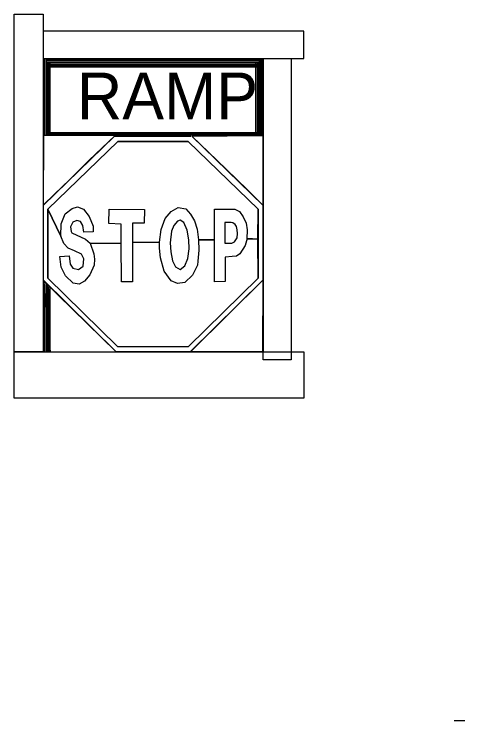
# Model space of a CAD drawing. Extents: x -0.162 to 0.195, y -0.006 to 0.263.
# Drawn here: x -0.1625 to -0.015, y -0.0064 to 0.2249 of the extents above; entities that cross this region are included whole.
import ezdxf

# ---------------------------------------------------------------- set-up
doc = ezdxf.new("R2010")
doc.units = 0
doc.layers.add('1', color=7, linetype='Continuous')
doc.layers.add('3', color=7, linetype='Continuous')

msp = doc.modelspace()

# ---------------------------------------------------------------- linework, layer by layer
at = {"layer": '1'}
msp.add_line((-0.015, -0.00638), (-0.0185, -0.00638), dxfattribs=at)
at = {"layer": '3'}
for p, q in [((-0.153, 0.21038), (-0.081, 0.21038)), ((-0.153, 0.21038), (-0.153, 0.11438)), ((-0.15275, 0.18488), (-0.15275, 0.21025)), ((-0.15238, 0.18513), (-0.15238, 0.21025)), ((-0.15188, 0.185), (-0.15188, 0.21025)), ((-0.15175, 0.21013), (-0.08188, 0.21013)), ((-0.15175, 0.20975), (-0.08188, 0.20975)), ((-0.15175, 0.20925), (-0.08188, 0.20925)), ((-0.1515, 0.20888), (-0.0825, 0.20888)), ((-0.1515, 0.185), (-0.1515, 0.20888)), ((-0.1515, 0.20838), (-0.0825, 0.20838)), ((-0.15113, 0.18613), (-0.15113, 0.20888)), ((-0.15063, 0.18613), (-0.15063, 0.20888)), ((-0.08338, 0.18613), (-0.08338, 0.20888)), ((-0.08288, 0.18613), (-0.08288, 0.20888)), ((-0.0825, 0.185), (-0.0825, 0.20888)), ((-0.08213, 0.185), (-0.08213, 0.21025)), ((-0.08175, 0.18513), (-0.08175, 0.21025)), ((-0.08138, 0.18488), (-0.08138, 0.21025)), ((-0.081, 0.21038), (-0.081, 0.11438)), ((-0.1515, 0.208), (-0.0825, 0.208)), ((-0.1515, 0.20763), (-0.0825, 0.20763)), ((-0.1515, 0.18613), (-0.081, 0.18613)), ((-0.1515, 0.18575), (-0.081, 0.18575)), ((-0.1515, 0.18538), (-0.081, 0.18538)), ((-0.12962, 0.18488), (-0.153, 0.16225)), ((-0.1285, 0.18313), (-0.15138, 0.161)), ((-0.12962, 0.18488), (-0.10462, 0.18488)), ((-0.1285, 0.18313), (-0.1055, 0.18313)), ((-0.1055, 0.18313), (-0.08263, 0.161)), ((-0.10437, 0.18488), (-0.081, 0.16225)), ((-0.15138, 0.1385), (-0.15138, 0.161)), ((-0.08263, 0.161), (-0.08263, 0.1385)), ((-0.153, 0.13787), (-0.12912, 0.11438)), ((-0.15275, 0.11438), (-0.15275, 0.13687)), ((-0.15238, 0.11438), (-0.15238, 0.13662)), ((-0.081, 0.13787), (-0.10487, 0.11438)), ((-0.15188, 0.11438), (-0.15188, 0.13637)), ((-0.1515, 0.11438), (-0.1515, 0.13612)), ((-0.15113, 0.11438), (-0.15113, 0.13562)), ((-0.15063, 0.11438), (-0.15063, 0.13512)), ((-0.081, 0.11438), (-0.12912, 0.11438)), ((-0.12912, 0.11438), (-0.081, 0.11438))]:
    msp.add_line(p, q, dxfattribs=at)
for points in [[(-0.153, 0.11438), (-0.16245, 0.11438), (-0.16245, 0.22485), (-0.153, 0.22485)], [(-0.153, 0.21038), (-0.06771, 0.21038), (-0.06771, 0.2193), (-0.153, 0.2193)], [(-0.081, 0.21038), (-0.07181, 0.21038), (-0.07181, 0.1117), (-0.081, 0.1117)], [(-0.12937, 0.18513), (-0.15288, 0.18513), (-0.153, 0.16237), (-0.14925, 0.166), (-0.14438, 0.17062), (-0.138, 0.177)], [(-0.10437, 0.18488), (-0.08113, 0.18513), (-0.081, 0.16225), (-0.08625, 0.1675), (-0.093, 0.174), (-0.096, 0.177)], [(-0.15138, 0.161), (-0.14715, 0.1522), (-0.14703, 0.15626), (-0.14572, 0.15949), (-0.14345, 0.16128), (-0.14177, 0.16176), (-0.13974, 0.16104), (-0.13795, 0.15865), (-0.13664, 0.15543), (-0.13664, 0.15364), (-0.13962, 0.15352), (-0.13998, 0.15567), (-0.1407, 0.15698), (-0.14189, 0.15734), (-0.14321, 0.15674), (-0.14404, 0.15531), (-0.14381, 0.15376), (-0.14357, 0.15328), (-0.13915, 0.15125), (-0.13759, 0.14993), (-0.12744, 0.14981), (-0.12744, 0.15615), (-0.1315, 0.15638), (-0.13138, 0.16104), (-0.11979, 0.16092), (-0.11991, 0.1565), (-0.12374, 0.1565), (-0.12374, 0.15017), (-0.1149, 0.15029), (-0.1143, 0.15435), (-0.11299, 0.15794), (-0.11107, 0.16033), (-0.1088, 0.16164), (-0.1063, 0.16116), (-0.10474, 0.15937), (-0.10343, 0.15722), (-0.10259, 0.15447), (-0.10211, 0.15101), (-0.09686, 0.15101), (-0.09686, 0.16104), (-0.09029, 0.16104), (-0.08874, 0.16033), (-0.08754, 0.15853), (-0.08658, 0.1565), (-0.08623, 0.15423), (-0.08635, 0.15137), (-0.08276, 0.15125), (-0.08263, 0.161), (-0.1055, 0.18313), (-0.1285, 0.18313)], [(-0.15138, 0.161), (-0.15138, 0.1385), (-0.1286, 0.11606), (-0.10545, 0.11606), (-0.08263, 0.1385), (-0.08276, 0.15125), (-0.08623, 0.15149), (-0.08682, 0.1491), (-0.08862, 0.14647), (-0.08969, 0.14563), (-0.09112, 0.14551), (-0.09338, 0.14532), (-0.09339, 0.13739), (-0.09686, 0.13727), (-0.09686, 0.15101), (-0.10211, 0.15101), (-0.10199, 0.14766), (-0.10235, 0.14408), (-0.10247, 0.14277), (-0.10415, 0.13942), (-0.10665, 0.13703), (-0.10897, 0.13672), (-0.11107, 0.13763), (-0.11334, 0.14074), (-0.11454, 0.14516), (-0.1149, 0.14826), (-0.1149, 0.15029), (-0.12374, 0.15017), (-0.12374, 0.13727), (-0.12732, 0.13727), (-0.12744, 0.14981), (-0.13759, 0.14993), (-0.1364, 0.14647), (-0.13616, 0.14468), (-0.13628, 0.14277), (-0.13771, 0.13954), (-0.13939, 0.13751), (-0.14118, 0.13655), (-0.14309, 0.13679), (-0.1456, 0.13918), (-0.14703, 0.14205), (-0.14751, 0.14551), (-0.1444, 0.14575), (-0.14416, 0.14301), (-0.14321, 0.14169), (-0.14142, 0.14133), (-0.13986, 0.14241), (-0.13962, 0.1448), (-0.14046, 0.14635), (-0.14273, 0.14742), (-0.14476, 0.14826), (-0.1462, 0.14981), (-0.14715, 0.1522)], [(-0.11098, 0.15386), (-0.11146, 0.15004), (-0.11124, 0.14709), (-0.11068, 0.14411), (-0.10968, 0.14222), (-0.10812, 0.14129), (-0.10662, 0.14252), (-0.10566, 0.14487), (-0.10518, 0.14802), (-0.10527, 0.15097), (-0.10582, 0.15422), (-0.10699, 0.15663), (-0.10812, 0.15741), (-0.10899, 0.15714), (-0.1102, 0.15575)], [(-0.09357, 0.15667), (-0.09354, 0.1499), (-0.0912, 0.14993), (-0.09032, 0.15035), (-0.08954, 0.15171), (-0.08934, 0.15306), (-0.08946, 0.15429), (-0.08976, 0.1554), (-0.09015, 0.15604), (-0.09087, 0.15658), (-0.0914, 0.15673)], [(-0.15288, 0.13762), (-0.15063, 0.11438), (-0.12912, 0.11438)], [(-0.10113, 0.1145), (-0.08113, 0.1145), (-0.081, 0.13787), (-0.10437, 0.11475), (-0.10475, 0.11438)], [(-0.16245, 0.11438), (-0.06771, 0.11438), (-0.06771, 0.09916), (-0.16245, 0.09916)]]:
    msp.add_lwpolyline(points, close=True, dxfattribs=at)

# ---------------------------------------------------------------- texts
msp.add_text('RAMP', height=0.01533, dxfattribs=at).set_placement((-0.14188, 0.19038))

doc.saveas('drawing.dxf')
